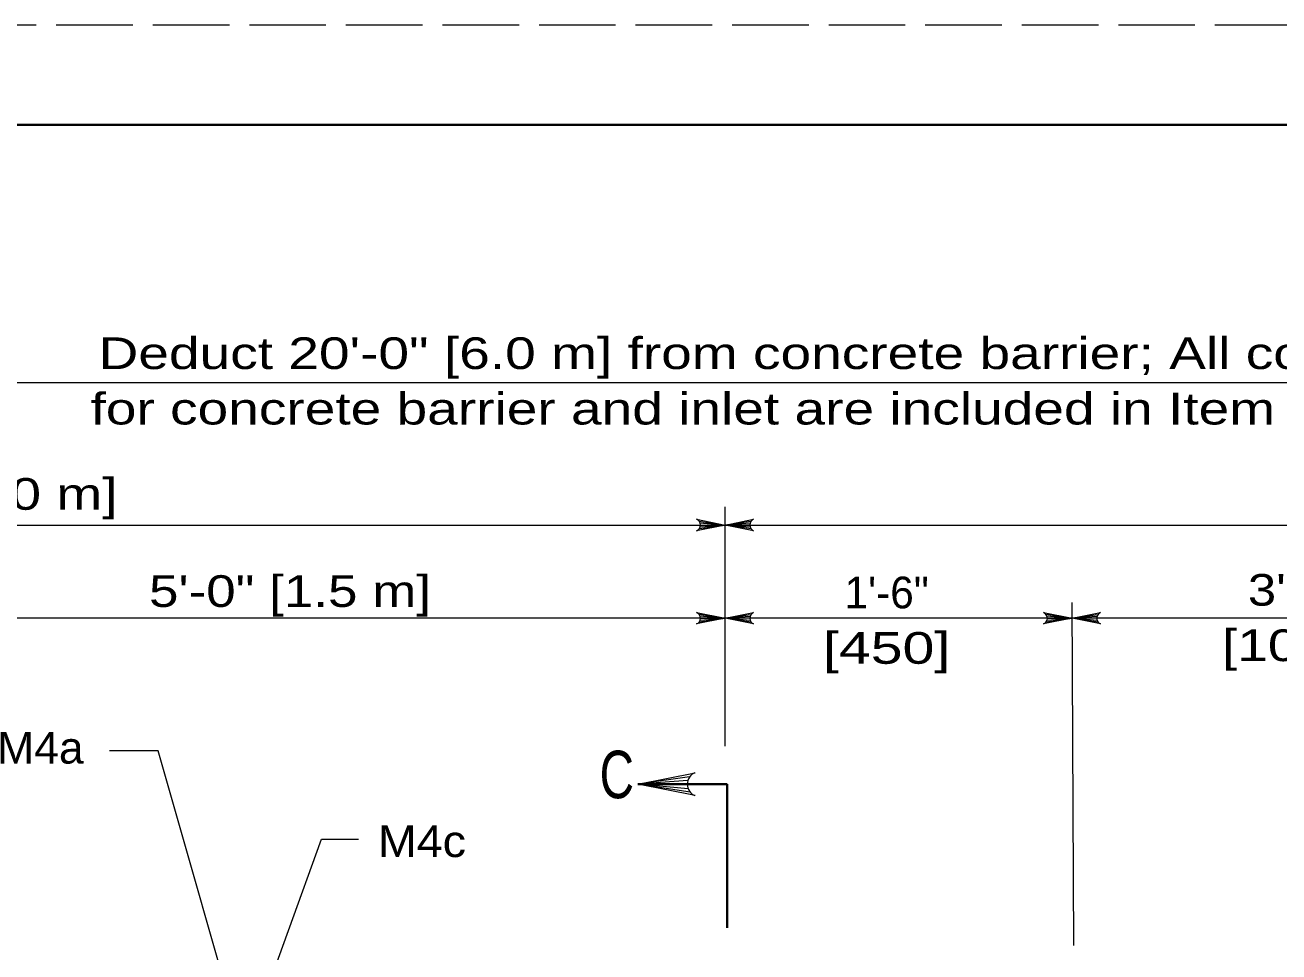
# Model space of a CAD drawing. Extents: x -1431.2 to -1397.2, y -1045.1 to -1001.1.
# Drawn here: x -1422.47 to -1416.18, y -1005.72 to -1001.08 of the extents above; entities that cross this region are included whole.
import ezdxf
from ezdxf.enums import TextEntityAlignment as Align

# ---------------------------------------------------------------- set-up
doc = ezdxf.new("R2010")
doc.units = 0
doc.header["$LTSCALE"] = 0.064
doc.linetypes.add('LONG_DASHED', pattern=[7.5, 6, -1.5])
doc.layers.add('1', color=7, linetype='Continuous', lineweight=13)

msp = doc.modelspace()

# ---------------------------------------------------------------- linework, layer by layer
at = {"layer": '1', "lineweight": 25}
msp.add_line((-1429.24575, -1001.57983), (-1397.74575, -1001.57983), dxfattribs=at)
at = {"layer": '1'}
for p, q in [((-1426.97675, -1002.87033), (-1410.9895, -1002.87033)), ((-1418.961, -1004.69267), (-1418.961, -1003.49383)), ((-1419.09192, -1003.56475), (-1418.961, -1003.58475)), ((-1419.08692, -1003.57317), (-1418.961, -1003.58475)), ((-1418.83167, -1003.56667), (-1418.961, -1003.58475)), ((-1418.836, -1003.57558), (-1418.961, -1003.58475)), ((-1426.97675, -1003.58475), (-1410.9895, -1003.58475)), ((-1419.09042, -1003.60283), (-1418.961, -1003.58475)), ((-1419.086, -1003.59392), (-1418.961, -1003.58475)), ((-1419.08467, -1003.58475), (-1418.961, -1003.58475)), ((-1418.83733, -1003.58475), (-1418.961, -1003.58475)), ((-1418.83508, -1003.59642), (-1418.961, -1003.58475)), ((-1418.83017, -1003.60475), (-1418.961, -1003.58475)), ((-1417.21217, -1005.69158), (-1417.222, -1003.97283)), ((-1414.96492, -1004.05217), (-1422.96592, -1004.05217)), ((-1419.09192, -1004.03217), (-1418.961, -1004.05217)), ((-1419.09042, -1004.07025), (-1418.961, -1004.05217)), ((-1419.08692, -1004.04058), (-1418.961, -1004.05217)), ((-1419.086, -1004.06133), (-1418.961, -1004.05217)), ((-1419.08467, -1004.05217), (-1418.961, -1004.05217)), ((-1418.83167, -1004.03408), (-1418.961, -1004.05217)), ((-1418.836, -1004.04308), (-1418.961, -1004.05217)), ((-1418.83733, -1004.05217), (-1418.961, -1004.05217)), ((-1418.83508, -1004.06383), (-1418.961, -1004.05217)), ((-1418.83017, -1004.07217), (-1418.961, -1004.05217)), ((-1417.35292, -1004.03217), (-1417.222, -1004.05217)), ((-1417.35133, -1004.07025), (-1417.222, -1004.05217)), ((-1417.34792, -1004.04058), (-1417.222, -1004.05217)), ((-1417.347, -1004.06133), (-1417.222, -1004.05217)), ((-1417.34567, -1004.05217), (-1417.222, -1004.05217)), ((-1417.09267, -1004.03408), (-1417.222, -1004.05217)), ((-1417.097, -1004.04308), (-1417.222, -1004.05217)), ((-1417.09833, -1004.05217), (-1417.222, -1004.05217)), ((-1417.09608, -1004.06383), (-1417.222, -1004.05217)), ((-1417.09108, -1004.07217), (-1417.222, -1004.05217)), ((-1419.13892, -1004.84733), (-1419.39767, -1004.88358)), ((-1419.14767, -1004.86525), (-1419.39767, -1004.88358)), ((-1419.15033, -1004.88358), (-1419.39767, -1004.88358)), ((-1419.14575, -1004.90683), (-1419.39767, -1004.88358)), ((-1419.13583, -1004.92358), (-1419.39767, -1004.88358))]:
    msp.add_line(p, q, dxfattribs=at)
at = {"layer": '1', "lineweight": 35}
for p, q in [((-1418.95117, -1004.88358), (-1419.39767, -1004.88358)), ((-1418.95117, -1005.60267), (-1418.95117, -1004.88358))]:
    msp.add_line(p, q, dxfattribs=at)
at = {"layer": '1', "linetype": 'LONG_DASHED'}
msp.add_lwpolyline([(-1431.24575, -1023.07983), (-1397.24575, -1023.07983), (-1397.24575, -1001.07983), (-1431.24575, -1001.07983)], close=True, dxfattribs=at)
at = {"layer": '1', "lineweight": 40}
msp.add_lwpolyline([(-1429.24575, -1001.57983), (-1397.74575, -1001.57983), (-1397.74575, -1022.57983), (-1429.24575, -1022.57983)], close=True, dxfattribs=at)
at = {"layer": '1'}
for points in [[(-1419.10392, -1003.55617), (-1418.961, -1003.58475), (-1419.10392, -1003.61333)], [(-1418.81817, -1003.61333), (-1418.961, -1003.58475), (-1418.81817, -1003.55617)], [(-1419.10392, -1004.02358), (-1418.961, -1004.05217), (-1419.10392, -1004.08075)], [(-1418.81817, -1004.08075), (-1418.961, -1004.05217), (-1418.81817, -1004.02358)], [(-1417.36492, -1004.02358), (-1417.222, -1004.05217), (-1417.36492, -1004.08075)], [(-1417.07908, -1004.08075), (-1417.222, -1004.05217), (-1417.07908, -1004.02358)], [(-1421.36042, -1006.267), (-1421.8035, -1004.7165), (-1422.0465, -1004.7165)], [(-1419.11183, -1004.94075), (-1419.39767, -1004.88358), (-1419.11183, -1004.82642)], [(-1421.31458, -1006.07475), (-1420.98408, -1005.15883), (-1420.79833, -1005.15883)]]:
    msp.add_lwpolyline(points, dxfattribs=at)
for centre, radius, start, end in [((-1419.11545, -1003.58479), 0.03084, 292.08782, 67.91395), ((-1418.80659, -1003.58473), 0.03084, 112.08782, 247.91395), ((-1419.11545, -1004.05222), 0.03084, 292.08782, 67.91395), ((-1418.80659, -1004.05216), 0.03084, 112.08782, 247.91395), ((-1417.37643, -1004.05222), 0.03084, 292.08782, 67.91395), ((-1417.06757, -1004.05216), 0.03084, 112.08782, 247.91395), ((-1419.08877, -1004.8835), 0.06168, 112.08782, 247.91395)]:
    msp.add_arc(centre, radius, start, end, dxfattribs=at)

# ---------------------------------------------------------------- texts
for s, width, p in [('Deduct 20\'-0" [6.0 m] from concrete barrier; All costs', 1.3, (-1418.90437, -1002.80333)), ('for concrete barrier and inlet are included in Item 604', 1.3, (-1418.90442, -1003.08117)), ('3\'-6"', 1.2, (-1416.08675, -1003.989)), ('[450]', 1.35, (-1418.15121, -1004.28017)), ('[1050]', 1.3, (-1416.08675, -1004.26683))]:
    msp.add_text(s, height=0.1588, dxfattribs=dict(at, width=width)).set_placement(p, align=Align.CENTER)
for s, height, width, p in [('10\'-0" [3.0 m]', 0.1588, 1.3, (-1423.63033, -1003.50842)), ('5\'-0" [1.5 m]', 0.1588, 1.25, (-1421.84883, -1003.99533)), ('M4a', 0.1588, 1.05, (-1422.61033, -1004.78008)), ('C', 0.2382, 0.75, (-1419.59, -1004.95392)), ('M4c', 0.1588, 1.1, (-1420.7015, -1005.24858))]:
    msp.add_text(s, height=height, dxfattribs=dict(at, width=width)).set_placement(p)
msp.add_text('1\'-6"', height=0.1588, dxfattribs=at).set_placement((-1418.15121, -1004.00233), align=Align.CENTER)

doc.saveas('drawing.dxf')
